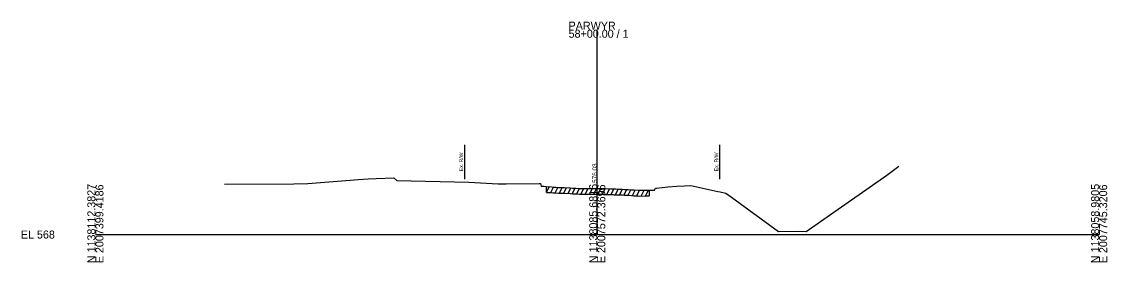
# Model space of a CAD drawing. Extents: x -2173 to 2007764, y -181 to 1138563.
# Drawn here: x 1017.4 to 1395.9, y 3490.3 to 3574.3 of the extents above; entities that cross this region are included whole.
import ezdxf

# ---------------------------------------------------------------- set-up
doc = ezdxf.new("R2010")
doc.units = 0
for name, color, linetype in [('Default', 7, 'Continuous'), ('RD_PD_Final_TrvlWay', 7, 'Continuous'), ('RD_PD_MedBWall', 7, 'Continuous'), ('RD_XS_ExPaveRet', 7, 'Continuous'), ('RD_XS_ExRW', 7, 'Continuous'), ('RD_XS_TX_Elev_EX', 7, 'Continuous')]:
    doc.layers.add(name, color=color, linetype=linetype)

msp = doc.modelspace()

# ---------------------------------------------------------------- linework, layer by layer
at = {"layer": 'RD_PD_Final_TrvlWay'}
msp.add_lwpolyline([(1088.08, 3517.57), (1112.31, 3517.69), (1117.12, 3517.77), (1134.88, 3519.2), (1138.19, 3519.5), (1141.04, 3519.59), (1147.14, 3519.78), (1148.16, 3518.87), (1173.33, 3518.28), (1183.49, 3517.72), (1184.21, 3517.73), (1186.38, 3517.75), (1197.87, 3517.87), (1198.32, 3517.82), (1198.56, 3516.94), (1199.45, 3516.84), (1200.4, 3516.73), (1202.11, 3516.63), (1202.55, 3516.58), (1203.68, 3516.52), (1204.57, 3516.45), (1206.07, 3516.43), (1206.6, 3516.42), (1208.62, 3516.3), (1209.46, 3516.24), (1210.64, 3516.16), (1211.93, 3516.1), (1212.61, 3516.11), (1214.32, 3516.1), (1214.69, 3516.09), (1215.65, 3516.09), (1216.72, 3516.07), (1218.1, 3516.05), (1218.74, 3516.05), (1220.43, 3516.04), (1220.76, 3516.03), (1222.79, 3516), (1223.3, 3515.96), (1223.62, 3515.93), (1223.98, 3515.92), (1224.62, 3515.9), (1225.83, 3515.85), (1226.83, 3515.81), (1227.61, 3515.77), (1228.86, 3515.72), (1230.01, 3515.62), (1230.88, 3515.57), (1232.4, 3515.47), (1232.9, 3515.44), (1234.96, 3515.46), (1235.41, 3515.46), (1235.73, 3515.46), (1236.14, 3515.54), (1237.2, 3515.51), (1238.09, 3515.46), (1238.35, 3516.18), (1238.79, 3516.21), (1242.75, 3516.63), (1245.86, 3516.93), (1248.57, 3517), (1250.72, 3517.08), (1260.17, 3515.06), (1261.01, 3514.87), (1262.92, 3514.48), (1264.87, 3513.04), (1281.26, 3501.12), (1288.37, 3501.15), (1290.91, 3501.12), (1319.06, 3520.71), (1323.3, 3523.83)], dxfattribs=at)
at = {"layer": 'RD_PD_MedBWall'}
for p, q in [((1218.1, 3500), (1218.1, 3571.5)), ((1043.1, 3500), (1218.1, 3500)), ((1218.1, 3500), (1393.1, 3500))]:
    msp.add_line(p, q, dxfattribs=at)
at = {"layer": 'RD_XS_ExPaveRet'}
for p, q in [((1200.4, 3514.73), (1200.4, 3516.73)), ((1200.4, 3514.73), (1201.37, 3516.67)), ((1200.4, 3514.73), (1202.11, 3514.63)), ((1201.9, 3514.64), (1202.86, 3516.56)), ((1202.11, 3514.63), (1202.55, 3514.58)), ((1202.55, 3514.58), (1203.68, 3514.52)), ((1203.4, 3514.54), (1204.37, 3516.47)), ((1203.68, 3514.52), (1204.57, 3514.45)), ((1204.57, 3514.45), (1206.07, 3514.43)), ((1204.9, 3514.45), (1205.89, 3516.43)), ((1206.07, 3514.43), (1206.6, 3514.42)), ((1206.4, 3514.42), (1207.38, 3516.37)), ((1206.6, 3514.42), (1208.62, 3514.3)), ((1207.9, 3514.34), (1208.87, 3516.28)), ((1208.62, 3514.3), (1209.46, 3514.24)), ((1209.4, 3514.25), (1210.37, 3516.18)), ((1209.46, 3514.24), (1210.64, 3514.16)), ((1210.64, 3514.16), (1211.93, 3514.1)), ((1210.9, 3514.15), (1211.88, 3516.1)), ((1211.93, 3514.1), (1212.61, 3514.11)), ((1212.4, 3514.11), (1213.4, 3516.11)), ((1212.61, 3514.11), (1214.32, 3514.1)), ((1213.9, 3514.1), (1214.89, 3516.09)), ((1214.32, 3514.1), (1214.69, 3514.09)), ((1214.69, 3514.09), (1215.65, 3514.09)), ((1215.4, 3514.09), (1216.4, 3516.08)), ((1215.65, 3514.09), (1216.72, 3514.07)), ((1216.72, 3514.07), (1218.1, 3514.05)), ((1216.9, 3514.07), (1217.89, 3516.06)), ((1218.1, 3514.05), (1218.74, 3514.05)), ((1218.4, 3514.05), (1219.4, 3516.05)), ((1218.74, 3514.05), (1220.43, 3514.04)), ((1219.9, 3514.04), (1220.89, 3516.03)), ((1220.43, 3514.04), (1220.76, 3514.03)), ((1220.76, 3514.03), (1222.79, 3514)), ((1221.4, 3514.02), (1222.39, 3516.01)), ((1222.79, 3514), (1223.3, 3513.96)), ((1222.9, 3513.99), (1223.87, 3515.92)), ((1223.3, 3513.96), (1223.62, 3513.93)), ((1223.62, 3513.93), (1223.98, 3513.92)), ((1223.98, 3513.92), (1224.62, 3513.9)), ((1224.4, 3513.9), (1225.38, 3515.87)), ((1224.62, 3513.9), (1225.83, 3513.85)), ((1225.83, 3513.85), (1226.83, 3513.81)), ((1225.9, 3513.85), (1226.88, 3515.81)), ((1226.83, 3513.81), (1227.61, 3513.77)), ((1227.4, 3513.78), (1228.38, 3515.74)), ((1227.61, 3513.77), (1228.86, 3513.72)), ((1228.86, 3513.72), (1230.01, 3513.62)), ((1228.9, 3513.72), (1229.86, 3515.63)), ((1230.01, 3513.62), (1230.88, 3513.57)), ((1230.4, 3513.6), (1231.37, 3515.54)), ((1230.88, 3513.57), (1232.4, 3513.47)), ((1231.9, 3513.5), (1232.87, 3515.44)), ((1232.4, 3513.47), (1232.9, 3513.44)), ((1232.9, 3513.44), (1234.96, 3513.46)), ((1233.4, 3513.45), (1234.41, 3515.45)), ((1234.9, 3513.46), (1235.92, 3515.5)), ((1234.96, 3513.46), (1235.41, 3513.46)), ((1235.41, 3513.46), (1235.73, 3513.46)), ((1235.73, 3513.46), (1236.14, 3513.54)), ((1236.14, 3515.54), (1236.14, 3513.54))]:
    msp.add_line(p, q, dxfattribs=at)
at = {"layer": 'RD_XS_ExRW'}
for p, q in [((1171.77, 3531.31), (1171.77, 3519.31)), ((1260.76, 3531.31), (1260.76, 3519.31))]:
    msp.add_line(p, q, dxfattribs=at)

# ---------------------------------------------------------------- texts
at = {"layer": 'Default'}
msp.add_text('-', height=0.0001, dxfattribs=at).set_placement((1043.1, 3500))
at = {"layer": 'RD_PD_MedBWall'}
for s, p in [('PARWYR', (1208.1, 3571.5)), ('58+00.00 / 1', (1208.1, 3568.7)), ('EL 568', (1017.1, 3498.6))]:
    msp.add_text(s, height=2.8, dxfattribs=at).set_placement(p)
for s, p in [('N 1138112.3827', (1043.1, 3490)), ('E 2007399.4186', (1045.9, 3490)), ('N 1138085.6816', (1218.1, 3490)), ('E 2007572.3696', (1220.9, 3490)), ('N 1138058.9805', (1393.1, 3490)), ('E 2007745.3206', (1395.9, 3490))]:
    msp.add_text(s, height=2.8, rotation=90, dxfattribs=at).set_placement(p)
at = {"layer": 'RD_XS_ExRW'}
for p in [(1171.27, 3522.08), (1260.26, 3522.08)]:
    msp.add_text('Ex. R/W ', height=1.3, rotation=90, dxfattribs=at).set_placement(p)
at = {"layer": 'RD_XS_TX_Elev_EX'}
msp.add_text('576.03', height=1.6, rotation=90, dxfattribs=at).set_placement((1218, 3518.05))

doc.saveas('drawing.dxf')
